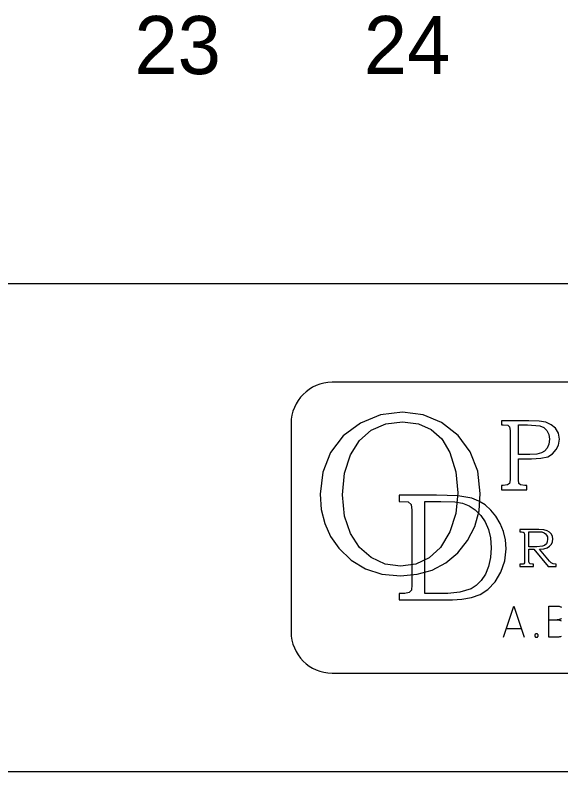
# Model space of a CAD drawing. Extents: x 0 to 841, y 0 to 594.
# Drawn here: x 486.2 to 533.2, y 15 to 80.1 of the extents above; entities that cross this region are included whole.
import ezdxf

# ---------------------------------------------------------------- set-up
doc = ezdxf.new("R2010")
doc.units = 0
for name, color, linetype in [('A1BORDER', 7, 'Continuous'), ('Level 1', 7, 'Continuous'), ('Level 10', 7, 'Continuous')]:
    doc.layers.add(name, color=color, linetype=linetype)

msp = doc.modelspace()

# ---------------------------------------------------------------- linework, layer by layer
at = {"layer": 'A1BORDER'}
for p, q in [((28, 57), (829, 57)), ((829, 15), (28, 15))]:
    msp.add_line(p, q, dxfattribs=at)
at = {"layer": 'Level 1'}
for points in [[(519.59, 45.93), (517.69, 45.7), (515.96, 45), (514.48, 43.9), (513.4, 42.47), (512.73, 40.77), (512.5, 38.87), (512.6, 37.57), (512.9, 36.37), (513.39, 35.25), (514.1, 34.25), (515.17, 33.2), (516.4, 32.45), (517.82, 32), (519.4, 31.87), (520.84, 32), (522.14, 32.35), (523.32, 32.97), (524.34, 33.83), (525.19, 34.9), (525.8, 36.1), (526.17, 37.45), (526.28, 38.95), (526.07, 40.85), (525.42, 42.53), (524.37, 43.93), (522.94, 45.03), (521.36, 45.7)], [(519.6, 45.1), (520.96, 44.93), (522.06, 44.45), (522.96, 43.63), (523.66, 42.47), (524.18, 40.8), (524.36, 39), (524.18, 37.23), (523.66, 35.63), (522.86, 34.3), (521.88, 33.4), (520.73, 32.87), (519.42, 32.7), (518.08, 32.87), (516.88, 33.43), (515.88, 34.3), (515.1, 35.5), (514.59, 37), (514.43, 38.83), (514.59, 40.7), (515.1, 42.27), (515.89, 43.5), (516.9, 44.37), (518.14, 44.93)], [(519.3, 38.25), (520.07, 38.23), (520.34, 38), (520.4, 37.5), (520.4, 31.07), (520.36, 30.63), (520.16, 30.43), (519.78, 30.35), (519.67, 30.35), (519.3, 30.35), (519.3, 29.8), (523.88, 29.8), (524.7, 29.85), (525.53, 30), (526.28, 30.25), (526.93, 30.67), (527.56, 31.33), (528.06, 32.17), (528.38, 33.15), (528.5, 34.17), (528.44, 34.95), (528.28, 35.67), (528, 36.37), (527.62, 37), (527.18, 37.5), (526.7, 37.95), (526.16, 38.27), (525.54, 38.53), (524.36, 38.73), (522.5, 38.8), (519.3, 38.8)], [(521.52, 30.35), (521.52, 38.25), (522.88, 38.25), (524.09, 38.23), (524.74, 38.1), (525.32, 37.87), (525.84, 37.53), (526.32, 37.05), (526.7, 36.5), (526.99, 35.85), (527.16, 35.13), (527.22, 34.27), (527.16, 33.43), (526.99, 32.67), (526.72, 32), (526.36, 31.45), (525.93, 31.03), (525.5, 30.73), (524.52, 30.45), (523.5, 30.35)], [(529.69, 35.83), (529.69, 35.63), (529.82, 35.63), (529.98, 35.6), (530.06, 35.55), (530.09, 35.37), (530.09, 33.13), (530.08, 32.97), (530.03, 32.9), (529.96, 32.87), (529.8, 32.87), (529.69, 32.87), (529.69, 32.67), (530.86, 32.67), (530.86, 32.87), (530.77, 32.87), (530.56, 32.9), (530.48, 32.97), (530.47, 33.13), (530.47, 34.15), (530.89, 34.15), (532.13, 32.67), (532.8, 32.67), (532.8, 32.87), (532.74, 32.87), (532.54, 32.9), (532.37, 32.97), (532.23, 33.13), (531.38, 34.15), (531.74, 34.17), (532.03, 34.27), (532.24, 34.4), (532.4, 34.57), (532.49, 34.77), (532.52, 35.03), (532.49, 35.25), (532.4, 35.45), (532.24, 35.6), (532.04, 35.73), (531.74, 35.8), (531.33, 35.83)], [(530.47, 35.63), (531.33, 35.63), (531.59, 35.63), (531.77, 35.55), (531.89, 35.47), (531.99, 35.35), (532.06, 35.2), (532.07, 35), (532.04, 34.77), (531.97, 34.6), (531.82, 34.47), (531.64, 34.4), (531.16, 34.35), (530.47, 34.35)]]:
    msp.add_lwpolyline(points, close=True, dxfattribs=at)
for points in [[(528.28, 26.57), (529.18, 29.26), (530.07, 26.57)], [(533.23, 26.64), (533.17, 26.61), (533.1, 26.6), (533.04, 26.59), (532.98, 26.57), (532.9, 26.57), (532.17, 26.57), (532.17, 29.26), (532.9, 29.26), (532.96, 29.26), (533.02, 29.25), (533.07, 29.24), (533.12, 29.23), (533.17, 29.2), (533.2, 29.19), (533.26, 29.15)], [(532.17, 28.06), (532.9, 28.06), (532.98, 28.06), (533.04, 28.06), (533.1, 28.04), (533.17, 28.03), (533.23, 28)], [(533.26, 28.17), (533.2, 28.15), (533.17, 28.13), (533.12, 28.1), (533.07, 28.09), (533.02, 28.07), (532.96, 28.06), (532.9, 28.06)], [(528.58, 27.33), (529.77, 27.33)], [(530.97, 26.73), (530.97, 26.71), (530.97, 26.7), (530.97, 26.69), (530.98, 26.67), (530.98, 26.66), (530.98, 26.65), (530.99, 26.64), (530.99, 26.63), (531, 26.61), (531.02, 26.61), (531.03, 26.6), (531.04, 26.59), (531.06, 26.59), (531.07, 26.59), (531.08, 26.57), (531.09, 26.57), (531.1, 26.57), (531.12, 26.57), (531.13, 26.57), (531.14, 26.57), (531.16, 26.57), (531.17, 26.59), (531.18, 26.59), (531.19, 26.59), (531.2, 26.6), (531.2, 26.61), (531.22, 26.61), (531.23, 26.63), (531.23, 26.64), (531.24, 26.65), (531.26, 26.66), (531.26, 26.67), (531.26, 26.69), (531.27, 26.7), (531.27, 26.71), (531.27, 26.73), (531.27, 26.74), (531.27, 26.75), (531.26, 26.76), (531.26, 26.77), (531.26, 26.79), (531.24, 26.8), (531.23, 26.81), (531.23, 26.81), (531.22, 26.83), (531.2, 26.84), (531.2, 26.85), (531.19, 26.85), (531.18, 26.86), (531.17, 26.86), (531.16, 26.86), (531.14, 26.87), (531.13, 26.87), (531.12, 26.87), (531.1, 26.87), (531.09, 26.87), (531.08, 26.86), (531.07, 26.86), (531.06, 26.86), (531.04, 26.85), (531.03, 26.85), (531.02, 26.84), (531, 26.83), (530.99, 26.81), (530.99, 26.81), (530.98, 26.8), (530.98, 26.79), (530.98, 26.77), (530.97, 26.76), (530.97, 26.75), (530.97, 26.74), (530.97, 26.73)]]:
    msp.add_lwpolyline(points, dxfattribs=at)
at = {"layer": 'Level 10'}
for p, q in [((571.47, 48.5), (513.54, 48.5)), ((510, 44.97), (510, 27.03)), ((513.54, 23.5), (571.47, 23.5)), ((513.54, 23.5), (513.54, 23.5))]:
    msp.add_line(p, q, dxfattribs=at)
for points in [[(528.1, 45.2), (528.1, 44.85), (528.24, 44.85), (528.66, 44.8), (528.79, 44.67), (528.84, 44.35), (528.84, 40.1), (528.79, 39.8), (528.63, 39.67), (528.24, 39.63), (528.1, 39.63), (528.1, 39.25), (530.29, 39.25), (530.29, 39.63), (530.1, 39.63), (529.74, 39.67), (529.6, 39.8), (529.57, 40.1), (529.57, 41.93), (530.68, 41.93), (531.49, 41.97), (532.08, 42.1), (532.49, 42.35), (532.82, 42.73), (533.02, 43.1), (533.09, 43.6), (533, 44.13), (532.76, 44.55), (532.38, 44.85), (531.92, 45.07), (531.36, 45.15), (530.46, 45.2)], [(529.57, 44.85), (530.34, 44.85), (531.4, 44.75), (531.74, 44.6), (532, 44.35), (532.19, 44), (532.24, 43.6), (532.19, 43.17), (532.04, 42.85), (531.82, 42.57), (531.56, 42.43), (531.14, 42.33), (530.53, 42.3), (529.57, 42.3)]]:
    msp.add_lwpolyline(points, close=True, dxfattribs=at)
for centre, start, end in [((513.535, 44.963), 90, 180), ((513.535, 27.03), 180, 270)]:
    msp.add_arc(centre, 3.535, start, end, dxfattribs=at)

# ---------------------------------------------------------------- texts
at = {"layer": 'Level 1'}
for s, p in [('23', (496.52, 75)), ('24', (516.26, 75))]:
    msp.add_text(s, height=5, dxfattribs=at).set_placement(p)

doc.saveas('drawing.dxf')
